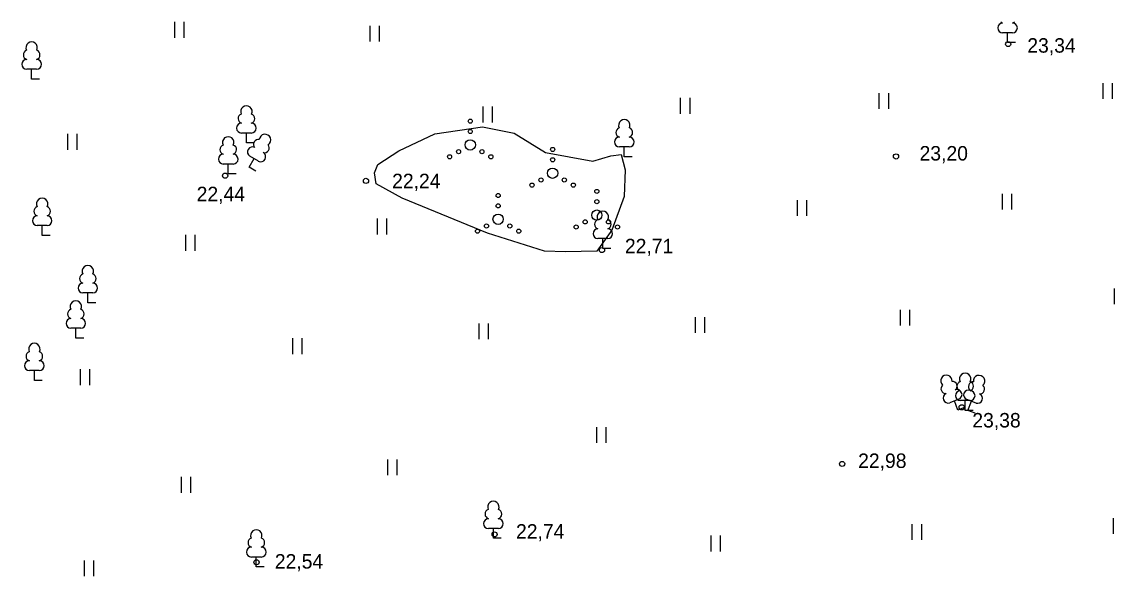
# Model space of a CAD drawing. Extents: x 714391 to 714584, y 6589993 to 6590151.
# Drawn here: x 714490.9 to 714543.8, y 6590124.2 to 6590151.1 of the extents above; entities that cross this region are included whole.
import ezdxf

# ---------------------------------------------------------------- set-up
doc = ezdxf.new("R2010")
doc.units = 0
for name, color, linetype in [('HALJASTUS', 7, 'Continuous'), ('KORGUS', 7, 'Continuous'), ('PUU', 7, 'Continuous')]:
    doc.layers.add(name, color=color, linetype=linetype)

msp = doc.modelspace()

# ---------------------------------------------------------------- linework, layer by layer
at = {"layer": 'HALJASTUS'}
for p, q in [((714498.282, 6590151.071), (714498.282, 6590150.309)), ((714498.738, 6590151.071), (714498.738, 6590150.309)), ((714507.742, 6590150.891), (714507.742, 6590150.129)), ((714508.198, 6590150.891), (714508.198, 6590150.129)), ((714543.242, 6590148.111), (714543.242, 6590147.349)), ((714543.698, 6590148.111), (714543.698, 6590147.349)), ((714532.402, 6590147.631), (714532.402, 6590146.869)), ((714532.858, 6590147.631), (714532.858, 6590146.869)), ((714513.222, 6590146.971), (714513.222, 6590146.209)), ((714513.678, 6590146.971), (714513.678, 6590146.209)), ((714522.782, 6590147.391), (714522.782, 6590146.629)), ((714523.238, 6590147.391), (714523.238, 6590146.629)), ((714493.102, 6590145.651), (714493.102, 6590144.889)), ((714493.558, 6590145.651), (714493.558, 6590144.889)), ((714538.362, 6590142.751), (714538.362, 6590141.989)), ((714538.818, 6590142.751), (714538.818, 6590141.989)), ((714528.442, 6590142.451), (714528.442, 6590141.689)), ((714528.898, 6590142.451), (714528.898, 6590141.689)), ((714508.102, 6590141.551), (714508.102, 6590140.789)), ((714508.558, 6590141.551), (714508.558, 6590140.789)), ((714498.822, 6590140.761), (714498.822, 6590139.999)), ((714499.278, 6590140.761), (714499.278, 6590139.999)), ((714543.792, 6590138.171), (714543.792, 6590137.409)), ((714533.422, 6590137.141), (714533.422, 6590136.379)), ((714533.878, 6590137.141), (714533.878, 6590136.379)), ((714513.022, 6590136.481), (714513.022, 6590135.719)), ((714513.478, 6590136.481), (714513.478, 6590135.719)), ((714523.502, 6590136.791), (714523.502, 6590136.029)), ((714523.958, 6590136.791), (714523.958, 6590136.029)), ((714504.002, 6590135.761), (714504.002, 6590134.999)), ((714504.458, 6590135.761), (714504.458, 6590134.999)), ((714493.712, 6590134.261), (714493.712, 6590133.499)), ((714494.168, 6590134.261), (714494.168, 6590133.499)), ((714518.722, 6590131.461), (714518.722, 6590130.699)), ((714519.178, 6590131.461), (714519.178, 6590130.699)), ((714508.602, 6590129.891), (714508.602, 6590129.129)), ((714509.058, 6590129.891), (714509.058, 6590129.129)), ((714498.612, 6590129.051), (714498.612, 6590128.289)), ((714499.068, 6590129.051), (714499.068, 6590128.289)), ((714543.742, 6590127.061), (714543.742, 6590126.299)), ((714534.002, 6590126.761), (714534.002, 6590125.999)), ((714534.458, 6590126.761), (714534.458, 6590125.999)), ((714524.262, 6590126.211), (714524.262, 6590125.449)), ((714524.718, 6590126.211), (714524.718, 6590125.449)), ((714493.912, 6590125.011), (714493.912, 6590124.249)), ((714494.368, 6590125.011), (714494.368, 6590124.249))]:
    msp.add_line(p, q, dxfattribs=at)
msp.add_lwpolyline([(714517.22, 6590139.95), (714516.21, 6590139.98), (714513.45, 6590140.85), (714509.32, 6590142.54), (714508.05, 6590143.24), (714507.97, 6590143.77), (714508.14, 6590144.17), (714509.15, 6590144.84), (714510.89, 6590145.66), (714513.2, 6590146), (714514.74, 6590145.69), (714516.26, 6590144.76), (714518.54, 6590144.34), (714519.41, 6590144.59), (714519.92, 6590144.65), (714520.11, 6590143.91), (714520.06, 6590142.62), (714519.47, 6590140.99), (714518.74, 6590139.98), (714517.22, 6590139.95)], dxfattribs=at)
for centre, radius in [((714512.61, 6590146.27), 0.1), ((714512.61, 6590145.77), 0.1), ((714512.61, 6590145.12), 0.25), ((714512.045, 6590144.795), 0.1), ((714513.175, 6590144.795), 0.1), ((714516.6, 6590144.9), 0.1), ((714511.61, 6590144.545), 0.1), ((714513.61, 6590144.545), 0.1), ((714516.6, 6590144.4), 0.1), ((714516.6, 6590143.75), 0.25), ((714515.6, 6590143.175), 0.1), ((714516.035, 6590143.425), 0.1), ((714517.165, 6590143.425), 0.1), ((714517.6, 6590143.175), 0.1), ((714513.96, 6590142.67), 0.1), ((714518.74, 6590142.87), 0.1), ((714513.96, 6590142.17), 0.1), ((714518.74, 6590142.37), 0.1), ((714513.96, 6590141.52), 0.25), ((714518.74, 6590141.72), 0.25), ((714513.395, 6590141.195), 0.1), ((714514.525, 6590141.195), 0.1), ((714517.74, 6590141.145), 0.1), ((714518.175, 6590141.395), 0.1), ((714519.305, 6590141.395), 0.1), ((714519.74, 6590141.145), 0.1), ((714512.96, 6590140.945), 0.1), ((714514.96, 6590140.945), 0.1)]:
    msp.add_circle(centre, radius, dxfattribs=at)
at = {"layer": 'KORGUS'}
for centre in [(714538.66, 6590150), (714533.23, 6590144.56), (714500.74, 6590143.63), (714507.56, 6590143.38), (714518.99, 6590140.03), (714536.41, 6590132.42), (714530.62, 6590129.68), (714513.79, 6590126.27), (714502.26, 6590124.92)]:
    msp.add_circle(centre, 0.125, dxfattribs=at)
at = {"layer": 'PUU'}
for p, q in [((714538.87, 6590150.545), (714538.39, 6590150.545)), ((714538.63, 6590150.07), (714538.63, 6590150.545)), ((714539.01, 6590150.07), (714538.63, 6590150.07)), ((714491.61, 6590148.785), (714491.13, 6590148.785)), ((714491.37, 6590148.31), (714491.37, 6590148.785)), ((714491.75, 6590148.31), (714491.37, 6590148.31)), ((714502.01, 6590145.695), (714501.53, 6590145.695)), ((714501.77, 6590145.22), (714501.77, 6590145.695)), ((714502.15, 6590145.22), (714501.77, 6590145.22)), ((714520.31, 6590145.025), (714519.83, 6590145.025)), ((714520.07, 6590144.55), (714520.07, 6590145.025)), ((714501.9, 6590144.05), (714502.141, 6590144.459)), ((714502.348, 6590144.337), (714501.934, 6590144.581)), ((714520.45, 6590144.55), (714520.07, 6590144.55)), ((714501.13, 6590144.195), (714500.65, 6590144.195)), ((714500.89, 6590143.72), (714500.89, 6590144.195)), ((714502.227, 6590143.857), (714501.9, 6590144.05)), ((714501.27, 6590143.72), (714500.89, 6590143.72)), ((714492.12, 6590141.215), (714491.64, 6590141.215)), ((714491.88, 6590140.74), (714491.88, 6590141.215)), ((714492.26, 6590140.74), (714491.88, 6590140.74)), ((714519.27, 6590140.585), (714518.79, 6590140.585)), ((714519.03, 6590140.11), (714519.03, 6590140.585)), ((714519.41, 6590140.11), (714519.03, 6590140.11)), ((714494.33, 6590137.955), (714493.85, 6590137.955)), ((714494.09, 6590137.48), (714494.09, 6590137.955)), ((714494.47, 6590137.48), (714494.09, 6590137.48)), ((714493.75, 6590136.245), (714493.27, 6590136.245)), ((714493.51, 6590135.77), (714493.51, 6590136.245)), ((714493.89, 6590135.77), (714493.51, 6590135.77)), ((714491.74, 6590134.195), (714491.26, 6590134.195)), ((714491.5, 6590133.72), (714491.5, 6590134.195)), ((714491.88, 6590133.72), (714491.5, 6590133.72)), ((714536.278, 6590132.82), (714535.831, 6590132.643)), ((714536.23, 6590132.29), (714536.055, 6590132.731)), ((714536.82, 6590132.745), (714536.34, 6590132.745)), ((714536.58, 6590132.27), (714536.58, 6590132.745)), ((714537.103, 6590132.629), (714536.655, 6590132.799)), ((714536.71, 6590132.27), (714536.879, 6590132.714)), ((714536.583, 6590132.43), (714536.23, 6590132.29)), ((714536.96, 6590132.27), (714536.58, 6590132.27)), ((714537.065, 6590132.135), (714536.71, 6590132.27)), ((714513.97, 6590126.555), (714513.49, 6590126.555)), ((714513.73, 6590126.08), (714513.73, 6590126.555)), ((714514.11, 6590126.08), (714513.73, 6590126.08)), ((714502.49, 6590125.175), (714502.01, 6590125.175)), ((714502.25, 6590124.7), (714502.25, 6590125.175)), ((714502.63, 6590124.7), (714502.25, 6590124.7))]:
    msp.add_line(p, q, dxfattribs=at)
for centre, radius, start, end in [((714538.393, 6590150.782), 0.238, 90.0016, 269.3953), ((714538.46, 6590151.243), 0.233, 225.9241, 253.1415), ((714538.8, 6590151.243), 0.233, 286.8508, 314.0736), ((714538.867, 6590150.782), 0.238, 270.6047, 89.9984), ((714491.37, 6590149.83), 0.277, 332.5799, 207.4201), ((714491.2, 6590149.483), 0.233, 109.0217, 253.1415), ((714491.54, 6590149.483), 0.233, 286.8508, 70.9859), ((714491.133, 6590149.022), 0.238, 90.0016, 269.3953), ((714491.607, 6590149.022), 0.238, 270.6047, 89.9984), ((714501.77, 6590146.74), 0.277, 332.5799, 207.4201), ((714501.6, 6590146.393), 0.233, 109.0217, 253.1415), ((714501.94, 6590146.393), 0.233, 286.8508, 70.9859), ((714501.533, 6590145.932), 0.238, 90.0016, 269.3953), ((714502.007, 6590145.932), 0.238, 270.6047, 89.9984), ((714519.9, 6590145.723), 0.233, 109.0217, 253.1415), ((714520.07, 6590146.07), 0.277, 332.5799, 207.4201), ((714520.24, 6590145.723), 0.233, 286.8508, 70.9859), ((714500.89, 6590145.24), 0.277, 332.5799, 207.4201), ((714502.349, 6590145.147), 0.233, 78.5084, 222.6283), ((714502.672, 6590145.359), 0.277, 302.0666, 176.9068), ((714519.833, 6590145.262), 0.238, 90.0016, 269.3953), ((714520.307, 6590145.262), 0.238, 270.6047, 89.9984), ((714500.72, 6590144.893), 0.233, 109.0217, 253.1415), ((714501.06, 6590144.893), 0.233, 286.8508, 70.9859), ((714502.057, 6590144.784), 0.238, 59.4883, 238.882), ((714502.642, 6590144.974), 0.233, 256.3375, 40.4726), ((714500.653, 6590144.432), 0.238, 90.0016, 269.3953), ((714501.127, 6590144.432), 0.238, 270.6047, 89.9984), ((714502.466, 6590144.543), 0.238, 240.0914, 59.4851), ((714491.88, 6590142.26), 0.277, 332.5799, 207.4201), ((714491.643, 6590141.452), 0.238, 90.0016, 269.3953), ((714491.71, 6590141.913), 0.233, 109.0217, 253.1415), ((714492.05, 6590141.913), 0.233, 286.8508, 70.9859), ((714492.117, 6590141.452), 0.238, 270.6047, 89.9984), ((714519.03, 6590141.63), 0.277, 332.5799, 207.4201), ((714518.86, 6590141.283), 0.233, 109.0217, 253.1415), ((714519.2, 6590141.283), 0.233, 286.8508, 70.9859), ((714518.793, 6590140.822), 0.238, 90.0016, 269.3953), ((714519.267, 6590140.822), 0.238, 270.6047, 89.9984), ((714494.09, 6590139), 0.277, 332.5799, 207.4201), ((714493.92, 6590138.653), 0.233, 109.0217, 253.1415), ((714494.26, 6590138.653), 0.233, 286.8508, 70.9859), ((714493.853, 6590138.192), 0.238, 90.0016, 269.3953), ((714494.327, 6590138.192), 0.238, 270.6047, 89.9984), ((714493.51, 6590137.29), 0.277, 332.5799, 207.4201), ((714493.34, 6590136.943), 0.233, 109.0217, 253.1415), ((714493.68, 6590136.943), 0.233, 286.8508, 70.9859), ((714493.273, 6590136.482), 0.238, 90.0016, 269.3953), ((714493.747, 6590136.482), 0.238, 270.6047, 89.9984), ((714491.5, 6590135.24), 0.277, 332.5799, 207.4201), ((714491.33, 6590134.893), 0.233, 109.0217, 253.1415), ((714491.67, 6590134.893), 0.233, 286.8508, 70.9859), ((714491.263, 6590134.432), 0.238, 90.0016, 269.3953), ((714491.737, 6590134.432), 0.238, 270.6047, 89.9984), ((714535.668, 6590133.702), 0.277, 354.262, 229.1022), ((714536.58, 6590133.79), 0.277, 332.5799, 207.4201), ((714537.25, 6590133.691), 0.277, 311.7549, 186.5951), ((714535.639, 6590133.317), 0.233, 130.7038, 274.8236), ((714535.955, 6590133.442), 0.233, 308.5329, 92.668), ((714536.187, 6590133.04), 0.238, 292.2868, 111.6805), ((714536.343, 6590132.982), 0.238, 90.0016, 269.3953), ((714536.41, 6590133.443), 0.233, 109.0217, 253.1415), ((714536.741, 6590133.02), 0.238, 69.1766, 248.5703), ((714536.968, 6590133.426), 0.233, 88.1967, 232.3165), ((714536.75, 6590133.443), 0.233, 286.8508, 70.9859), ((714536.817, 6590132.982), 0.238, 270.6047, 89.9984), ((714537.286, 6590133.306), 0.233, 266.0258, 50.1609), ((714535.746, 6590132.864), 0.238, 111.6837, 291.0774), ((714537.185, 6590132.852), 0.238, 249.7797, 69.1734), ((714513.73, 6590127.6), 0.277, 332.5799, 207.4201), ((714513.56, 6590127.253), 0.233, 109.0217, 253.1415), ((714513.9, 6590127.253), 0.233, 286.8508, 70.9859), ((714513.493, 6590126.792), 0.238, 90.0016, 269.3953), ((714513.967, 6590126.792), 0.238, 270.6047, 89.9984), ((714502.25, 6590126.22), 0.277, 332.5799, 207.4201), ((714502.08, 6590125.873), 0.233, 109.0217, 253.1415), ((714502.42, 6590125.873), 0.233, 286.8508, 70.9859), ((714502.013, 6590125.412), 0.238, 90.0016, 269.3953), ((714502.487, 6590125.412), 0.238, 270.6047, 89.9984)]:
    msp.add_arc(centre, radius, start, end, dxfattribs=at)

# ---------------------------------------------------------------- texts
at = {"layer": 'KORGUS'}
for s, p in [('23,34', (714539.586, 6590149.585)), ('23,20', (714534.369, 6590144.365)), ('22,24', (714508.826, 6590143.025)), ('22,44', (714499.361, 6590142.395)), ('22,71', (714520.1, 6590139.875)), ('23,38', (714536.924, 6590131.445)), ('22,98', (714531.394, 6590129.485)), ('22,74', (714514.826, 6590126.065)), ('22,54', (714503.146, 6590124.615))]:
    msp.add_text(s, height=0.7, dxfattribs=at).set_placement(p)

doc.saveas('drawing.dxf')
